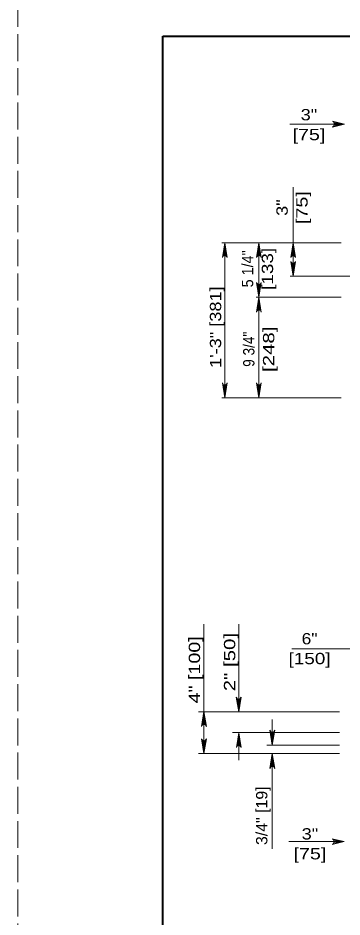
# Model space of a CAD drawing. Extents: x 1352.5 to 1386.5, y 735.9 to 779.9.
# Drawn here: x 1352.51 to 1356.98, y 745.27 to 757.67 of the extents above; entities that cross this region are included whole.
import ezdxf
from ezdxf.enums import TextEntityAlignment as Align

# ---------------------------------------------------------------- set-up
doc = ezdxf.new("R2010")
doc.units = 0
doc.header["$LTSCALE"] = 0.062
doc.linetypes.add('LONG_DASHED', pattern=[7.5, 6, -1.5])
doc.layers.add('1', color=7, linetype='Continuous', lineweight=13)

msp = doc.modelspace()

# ---------------------------------------------------------------- linework, layer by layer
at = {"layer": '1', "lineweight": 25}
msp.add_line((1354.513, 757.41967), (1386.013, 757.41967), dxfattribs=at)
at = {"layer": '1'}
for p, q in [((1357.017, 756.20658), (1356.26483, 756.20658)), ((1356.86683, 756.17792), (1357.017, 756.20658)), ((1356.86858, 756.23258), (1357.017, 756.20658)), ((1356.87258, 756.18992), (1357.017, 756.20658)), ((1356.87367, 756.21975), (1357.017, 756.20658)), ((1356.87517, 756.20658), (1357.017, 756.20658)), ((1356.309, 754.56975), (1356.309, 755.33783)), ((1356.97333, 754.56975), (1355.32567, 754.56975)), ((1355.34208, 754.38208), (1355.365, 754.56975)), ((1355.35167, 754.38917), (1355.365, 754.56975)), ((1355.365, 754.3925), (1355.365, 754.56975)), ((1355.3755, 754.39058), (1355.365, 754.56975)), ((1355.38575, 754.38425), (1355.365, 754.56975)), ((1355.365, 754.56975), (1355.365, 752.44933)), ((1355.81408, 754.38208), (1355.837, 754.56975)), ((1355.82367, 754.38917), (1355.837, 754.56975)), ((1355.837, 754.3925), (1355.837, 754.56975)), ((1355.8475, 754.39058), (1355.837, 754.56975)), ((1355.85775, 754.38425), (1355.837, 754.56975)), ((1355.837, 754.56975), (1355.837, 752.44933)), ((1356.28608, 754.38208), (1356.309, 754.56975)), ((1356.29567, 754.38917), (1356.309, 754.56975)), ((1356.309, 754.3925), (1356.309, 754.56975)), ((1356.3195, 754.39058), (1356.309, 754.56975)), ((1356.32975, 754.38425), (1356.309, 754.56975)), ((1356.309, 754.56975), (1356.309, 754.107)), ((1356.28825, 754.2925), (1356.309, 754.107)), ((1356.2985, 754.28617), (1356.309, 754.107)), ((1356.332, 754.29467), (1356.309, 754.107)), ((1356.32233, 754.28758), (1356.309, 754.107)), ((1356.309, 754.28425), (1356.309, 754.107)), ((1357.25742, 754.107), (1356.26967, 754.107)), ((1357.55133, 754.107), (1356.56358, 754.107)), ((1355.81625, 754.00325), (1355.837, 753.81775)), ((1355.8265, 753.997), (1355.837, 753.81775)), ((1355.86, 754.0055), (1355.837, 753.81775)), ((1355.85033, 753.99833), (1355.837, 753.81775)), ((1355.837, 753.99508), (1355.837, 753.81775)), ((1356.97333, 753.81775), (1355.79767, 753.81775)), ((1355.81408, 753.62992), (1355.837, 753.81767)), ((1355.82367, 753.63708), (1355.837, 753.81767)), ((1355.837, 753.64033), (1355.837, 753.81767)), ((1355.8475, 753.63842), (1355.837, 753.81767)), ((1355.85775, 753.63217), (1355.837, 753.81767)), ((1355.34425, 752.61492), (1355.365, 752.42942)), ((1355.3545, 752.60858), (1355.365, 752.42942)), ((1355.388, 752.61708), (1355.365, 752.42942)), ((1355.37833, 752.61), (1355.365, 752.42942)), ((1355.365, 752.60667), (1355.365, 752.42942)), ((1355.81625, 752.61492), (1355.837, 752.42942)), ((1355.8265, 752.60858), (1355.837, 752.42942)), ((1355.86, 752.61708), (1355.837, 752.42942)), ((1355.85033, 752.61), (1355.837, 752.42942)), ((1355.837, 752.60667), (1355.837, 752.42942)), ((1356.97333, 752.42942), (1355.32567, 752.42942)), ((1355.07875, 749.30492), (1355.07875, 747.52142)), ((1355.55783, 748.09983), (1355.55783, 749.30492)), ((1355.53658, 748.28242), (1355.55742, 748.09692)), ((1355.54692, 748.27617), (1355.55742, 748.09692)), ((1355.58033, 748.28458), (1355.55742, 748.09692)), ((1355.57075, 748.2775), (1355.55742, 748.09692)), ((1355.55742, 748.27425), (1355.55742, 748.09692)), ((1356.94892, 748.09983), (1355.00217, 748.09983)), ((1355.05583, 747.91383), (1355.07875, 748.1015)), ((1355.06542, 747.92092), (1355.07875, 748.1015)), ((1355.07875, 747.92417), (1355.07875, 748.1015)), ((1355.08925, 747.92225), (1355.07875, 748.1015)), ((1355.0995, 747.916), (1355.07875, 748.1015)), ((1356.02167, 747.99058), (1356.02167, 747.78992)), ((1356.94892, 747.81058), (1355.47417, 747.81058)), ((1355.53508, 747.62242), (1355.558, 747.81017)), ((1355.54467, 747.62958), (1355.558, 747.81017)), ((1355.55783, 747.81058), (1355.55783, 747.43083)), ((1355.558, 747.63283), (1355.558, 747.81017)), ((1355.5685, 747.63092), (1355.558, 747.81017)), ((1355.57875, 747.62467), (1355.558, 747.81017)), ((1356.00092, 747.82433), (1356.02167, 747.63883)), ((1356.01125, 747.81808), (1356.02167, 747.63883)), ((1356.04467, 747.8265), (1356.02167, 747.63883)), ((1356.035, 747.81942), (1356.02167, 747.63883)), ((1356.02167, 747.81617), (1356.02167, 747.63883)), ((1355.058, 747.70808), (1355.07875, 747.52258)), ((1355.06825, 747.70175), (1355.07875, 747.52258)), ((1355.10175, 747.71025), (1355.07875, 747.52258)), ((1355.09208, 747.70317), (1355.07875, 747.52258)), ((1355.07875, 747.69992), (1355.07875, 747.52258)), ((1356.94892, 747.63708), (1355.94617, 747.63708)), ((1356.94892, 747.52142), (1355.00217, 747.52142)), ((1355.99875, 747.3355), (1356.02167, 747.52317)), ((1356.00833, 747.34258), (1356.02167, 747.52317)), ((1356.02167, 747.52317), (1356.02167, 746.20833)), ((1356.02167, 747.34583), (1356.02167, 747.52317)), ((1356.03217, 747.34392), (1356.02167, 747.52317)), ((1356.0425, 747.33767), (1356.02167, 747.52317)), ((1356.24792, 746.30708), (1357.00283, 746.30708)), ((1356.86167, 746.27833), (1357.01183, 746.30708)), ((1356.86342, 746.333), (1357.01183, 746.30708)), ((1356.86733, 746.29042), (1357.01183, 746.30708)), ((1356.86842, 746.32017), (1357.01183, 746.30708)), ((1356.87, 746.30708), (1357.01183, 746.30708))]:
    msp.add_line(p, q, dxfattribs=at)
at = {"layer": '1', "linetype": 'LONG_DASHED'}
msp.add_lwpolyline([(1352.513, 735.91967), (1386.513, 735.91967), (1386.513, 757.91967), (1352.513, 757.91967)], close=True, dxfattribs=at)
at = {"layer": '1', "lineweight": 25}
msp.add_lwpolyline([(1386.013, 736.41967), (1354.513, 736.41967), (1354.513, 757.41967)], dxfattribs=at)
at = {"layer": '1', "lineweight": 40}
msp.add_lwpolyline([(1354.513, 757.41967), (1386.013, 757.41967), (1386.013, 736.41967), (1354.513, 736.41967)], close=True, dxfattribs=at)
msp.add_lwpolyline([(1354.513, 757.41967), (1386.013, 757.41967), (1386.013, 736.41967), (1354.513, 736.41967)], close=True, dxfattribs=at)
at = {"layer": '1'}
for points in [[(1356.85308, 756.16567), (1357.017, 756.20658), (1356.85308, 756.24758)], [(1355.33225, 754.36483), (1355.365, 754.56975), (1355.39783, 754.36483)], [(1355.80425, 754.36483), (1355.837, 754.56975), (1355.86983, 754.36483)], [(1356.27625, 754.36483), (1356.309, 754.56975), (1356.34183, 754.36483)], [(1356.34183, 754.31192), (1356.309, 754.107), (1356.27625, 754.31192)], [(1355.86983, 754.02267), (1355.837, 753.81775), (1355.80425, 754.02267)], [(1355.80425, 753.61275), (1355.837, 753.81767), (1355.86983, 753.61275)], [(1355.39783, 752.63433), (1355.365, 752.42942), (1355.33225, 752.63433)], [(1355.86983, 752.63433), (1355.837, 752.42942), (1355.80425, 752.63433)], [(1356.2885, 748.96792), (1357.37483, 748.96792), (1357.60467, 748.96792)], [(1355.59017, 748.30183), (1355.55742, 748.09692), (1355.52458, 748.30183)], [(1355.046, 747.89658), (1355.07875, 748.1015), (1355.11158, 747.89658)], [(1355.52525, 747.60525), (1355.558, 747.81017), (1355.59075, 747.60525)], [(1356.0545, 747.84375), (1356.02167, 747.63883), (1355.98892, 747.84375)], [(1355.11158, 747.7275), (1355.07875, 747.52258), (1355.046, 747.7275)], [(1355.98892, 747.31825), (1356.02167, 747.52317), (1356.0545, 747.31825)], [(1356.84792, 746.26608), (1357.01183, 746.30708), (1356.84792, 746.348)]]:
    msp.add_lwpolyline(points, dxfattribs=at)
for centre, major_axis, start_param, end_param in [((1356.83986, 756.20666), (0, 0.04422), 3.52706694, 5.89768008), ((1355.36506, 754.34832), (0, 0.04422), 5.0978942, 7.46850734), ((1355.83706, 754.34832), (0, 0.04422), 5.0978942, 7.46850734), ((1356.30905, 754.34832), (0, 0.04422), 5.0978942, 7.46850734), ((1356.30898, 754.32843), (0, -0.04422), 5.0978942, 7.46850734), ((1355.83699, 754.03922), (0, -0.04422), 5.0978942, 7.46850734), ((1355.83706, 753.5962), (0, 0.04422), 5.0978942, 7.46850734), ((1355.36498, 752.65084), (0, -0.04422), 5.0978942, 7.46850734), ((1355.83699, 752.65084), (0, -0.04422), 5.0978942, 7.46850734), ((1355.55735, 748.31835), (0, -0.04422), 5.0978942, 7.46850734), ((1355.07881, 747.88004), (0, 0.04422), 5.0978942, 7.46850734), ((1356.02167, 747.8603), (0, -0.04422), 5.0978942, 7.46850734), ((1355.07874, 747.74402), (0, -0.04422), 5.0978942, 7.46850734), ((1355.55804, 747.58869), (0, 0.04422), 5.0978942, 7.46850734), ((1356.02174, 747.30171), (0, 0.04422), 5.0978942, 7.46850734), ((1356.83465, 746.30709), (0, 0.04422), 3.52706694, 5.89768008)]:
    msp.add_ellipse(centre, major_axis=major_axis, ratio=0.8, start_param=start_param, end_param=end_param, dxfattribs=at)

# ---------------------------------------------------------------- texts
for s, width, p in [('3"', 1.2, (1356.52671, 756.25758)), ('[75]', 1.3, (1356.52671, 755.98358)), ('6"', 1.15, (1356.53517, 749.02883)), ('[150]', 1.25, (1356.53517, 748.75483)), ('3"', 1.2, (1356.54021, 746.33658)), ('[75]', 1.3, (1356.54021, 746.06258))]:
    msp.add_text(s, height=0.156, dxfattribs=dict(at, width=width)).set_placement(p, align=Align.CENTER)
for s, width, p in [('[75]', 1.3, (1356.50775, 755.05404)), ('3"', 1.2, (1356.23375, 755.05404)), ('5 1/4"', 0.95, (1355.75808, 754.20892)), ('[133]', 1.25, (1356.03208, 754.20892)), ('9 3/4"', 0.9, (1355.77475, 753.0995)), ('[248]', 1.35, (1356.04875, 753.09946))]:
    msp.add_text(s, height=0.156, rotation=90, dxfattribs=dict(at, width=width)).set_placement(p, align=Align.CENTER)
for s, width, p in [('1\'-3" [381]', 1.2, (1355.31592, 752.84217)), ('4" [100]', 1.3, (1355.02483, 748.21467)), ('2" [50]', 1.35, (1355.51017, 748.38142)), ('3/4" [19]', 1.05, (1355.95325, 746.26025))]:
    msp.add_text(s, height=0.156, rotation=90, dxfattribs=dict(at, width=width)).set_placement(p)

doc.saveas('drawing.dxf')
